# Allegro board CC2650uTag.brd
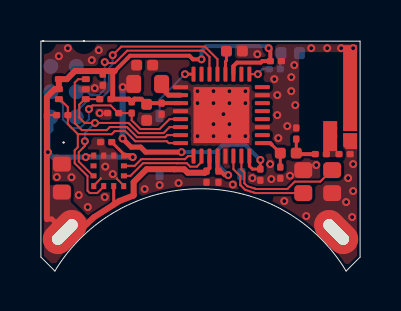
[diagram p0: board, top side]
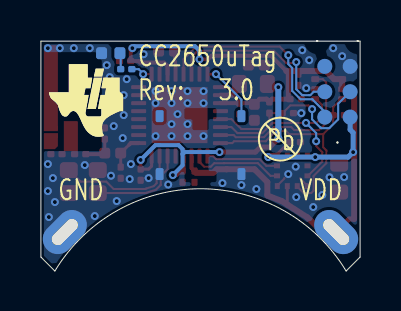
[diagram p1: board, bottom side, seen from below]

Outline 16 x 11.5 mm; copper layers: TOP, BOTTOM. Coordinates in mm from the lower left corner of the outline.
Outline path: 0,11.5 0,0.7 0.7,0 arc(8,4.12) 15.3,0 16,0.7 16,11.5 0,11.5

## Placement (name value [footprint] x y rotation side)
A1  2450AT07A0100  [ANTENNA_2450AT07A0100N]  14.7 6.75 0 top
C1  22uF  [CAPC1608X90L]  1.05 3.95 90 top
C2  100nF  [CAPC0603X35L]  11.5 10.5 0 top
C3  100nF  [CAPC0603X35L]  8.3 5 270 top
C4  10uF  [CAPC1005X60L]  5.3 8.34 270 top
C5  100nF  [CAPC0603X35L]  6.05 8.4 270 top
C6  10uF  [CAPC1005X60L]  4.8 10.3 0 top
C7  100nF  [CAPC0603X35L]  8.9 5 270 top
C8  100nF  [CAPC0603X35L]  11 5.1 270 top
C9  100nF  [CAPC0603X35L]  3.9 7.9 180 top
C11  1.2pF  [CAPC0603X35L]  12 5.2 270 top
C12  1.2pF  [CAPC0603X35L]  12.8 6.6 90 top
C13  12pF  [CAPC0603X35L]  13.75 5.85 0 top
C14  DNM  [CAPC0603X35L]  15.5 5.85 180 top
C19  1uF  [CAPC1005X60L]  9.3 11 0 top
C21  100nF  [CAPC0603X35L]  3.55 6.45 180 top
C41  100nF  [CAPC0603X35L]  3.1 9.85 270 top
CR1  LWQH8G-Q2S2-3K5L-1  [LED_LWQH8GQ2S23K5L1L]  12.96 10.9 180 bottom
L1  10uH  [INDC1608X100L]  6.05 9.36 180 top
L11  2nH  [INDC1005X60L]  12 5.9 0 top
NOREF  -  []  0 6.32 0 top
NOREF#2  -  []  15.3 0 90 top
NOREF#3  -  []  14.6 10.35 180 bottom
P1  TC2030-CTX-NL  [TAGCONNECT_TC2030-CTX-NLL]  0.5 7.7 90 bottom
R1  102k  [RESC0603X35L]  4.55 7.9 90 top
R2  2.2k  [RESC0603X35L]  1.35 7.8 180 top
R3  2.2k  [RESC0603X35L]  2.95 8.6 0 top
R4  150  [RESC0603X35L]  12 10.1 180 bottom
SP1  CUSTOM_BATTERY_CONN  [PAD_S2800OBL5000_800M3000]  1.2 1.95 315 top
SP2  CUSTOM_BATTERY_CONN  [PAD_S2800OBL5000_800M3000]  14.8 1.95 45 top
SW2  EVQP6LB55  [SW_EVQP6LB55L]  5.95 4.85 90 bottom
U1  CC26XX_4X4  [QFNFC40P400X400X100-33L]  11.1 6.4 90 top
U2  KX022-1020  [LGAFC12S50P200X200X100]  2.65 4.25 0 top
U4  TMP102  [SOTFL50P160X60-6AL]  2.25 8.6 90 top
Y2  24MHz  [XTAL_FA128L]  13.15 3.9 0 top

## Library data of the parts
A1 = ANTENNA_CERAMIC_4: alternate symbols: (ANTENNA_2450AT07A0100L,ANTENNA_2450AT07A0100M)
C1 = CAPACITOR: alternate symbols: (CAPC1608X90L,CAPC1608X90M)
C2 C3 C5 C7-C9 C11-C13 C21 C41 = CAPACITOR: alternate symbols: (CAPC0603X35L,CAPC0603X35M)
C4 C6 C19 = CAPACITOR: alternate symbols: (CAPC1005X60L,CAPC1005X60M)
C14 = CAPACITOR: alternate symbols: (CAPC0603X35L,CAPC0603X35N)
CR1 = LED: User Part Number: #PN; alternate symbols: (LED_LWQH8GQ2S23K5L1L,LED_LWQH8GQ2S23K5L1M)
L1 = INDUCTOR: alternate symbols: (INDC1608X100L,INDC1608X100M)
L11 = INDUCTOR: alternate symbols: (INDC1005X60L,INDC1005X60M)
P1 = CONN_IDC_TC2030-CTX-NL_0: alternate symbols: (TAGCONNECT_TC2030-CTX-NLL,TAGCONNECT_TC2030-CTX-NLM)
R1-R4 = RESISTOR: alternate symbols: (RESC0603X35L,RESC0603X35M)
SP1 SP2 = SINGLEPAD
SW2 = SWITCH_TACT: User Part Number: #PN; alternate symbols: (SW_EVQP6LB55L,SW_EVQP6LB55M)
U1 = IC_RF_CC26XX_QFN32_2: alternate symbols: (QFNFC40P400X400X100-33L,QFNFC40P400X400X100-33M)
U2 = IC_ACC_KX022-1020_LGA12: User Part Number: #PN
U4 = IC_PERIPH_TMP102_SOT563: User Part Number: #PN; alternate symbols: (SOTFL50P160X60-6AL,SOTFL50P160X60-6AM)
Y2 = XTAL_4: alternate symbols: (XTAL_FA128L,XTAL_FA128M)

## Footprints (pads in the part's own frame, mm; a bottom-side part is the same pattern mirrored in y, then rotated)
ANTENNA_2450AT07A0100N
  custom 0.062x0.062 smd: 1(0,0) 2(0.6,0) 3(0.6,0.4) 4(0,0.4)
CAPC0603X35L
  custom 0.08x0.08 smd: 1(0,0) 2(0.56,0)
CAPC1005X60L
  custom 0.135x0.135 smd: 1(0,0) 2(0.8,0)
CAPC1608X90L
  custom 0.188x0.188 smd: 1(0,0) 2(1.4,0)
INDC1005X60L
  custom 0.135x0.135 smd: 1(0,0) 2(0.8,0)
INDC1608X100L
  custom 0.188x0.188 smd: 1(0,0) 2(1.4,0)
LED_LWQH8GQ2S23K5L1L
  custom 0.138x0.138 smd: 1(0,0) 2(0.92,0)
LGAFC12S50P200X200X100
  rect 0.25x0.3 smd: 1(0,0) 2(0.5,0) 3(1,0) 4(1.5,0) 7(1.5,1.526) 8(1,1.526) 9(0.5,1.526) 10(0,1.526)
  rect 0.3x0.25 smd: 5(1.512,0.513) 6(1.512,1.013) 11(-0.012,1.013) 12(-0.012,0.513)
PAD_S2800OBL5000_800M3000
  oval 1.5x2.5 hole 0.6x1.6: 1(0,0)
QFNFC40P400X400X100-33L
  custom 0.05x0.05 smd: 1(0,0) 2(0.4,0) 3(0.8,0) 4(1.2,0) 5(1.6,0) 6(2,0) 7(2.4,0) 8(2.8,0) 9(3.45,0.65) 10(3.45,1.05) 11(3.45,1.45) 12(3.45,1.85) 13(3.45,2.25) 14(3.45,2.65) 15(3.45,3.05) 16(3.45,3.45) 17(2.8,4.1) 18(2.4,4.1) 19(2,4.1) 20(1.6,4.1) 21(1.2,4.1) 22(0.8,4.1) 23(0.4,4.1) 24(0,4.1) 25(-0.65,3.45) 26(-0.65,3.05) 27(-0.65,2.65) 28(-0.65,2.25) 29(-0.65,1.85) 30(-0.65,1.45) 31(-0.65,1.05) 32(-0.65,0.65)
  rect 2.799x2.799 smd: 33(1.4,2.05)
RESC0603X35L
  custom 0.08x0.08 smd: 1(0,0) 2(0.56,0)
SOTFL50P160X60-6AL
  custom 0.075x0.075 smd: 1(0,0) 2(0.5,0) 3(1,0) 4(1,1.35) 5(0.5,1.35) 6(0,1.35)
SW_EVQP6LB55L
  custom 0.1x0.1 smd: 1(0,0) 2(2.9,0) 3(2.9,4.1) 4(0,4.1)
TAGCONNECT_TC2030-CTX-NLL
  round 0.1 hole 1 unplated: (-1.27,0.635) (3.81,-0.381) (3.81,1.651)
  round 0.75 smd: 1(0,0) 2(0,1.27) 3(1.27,0) 4(1.27,1.27) 5(2.54,0) 6(2.54,1.27)
XTAL_FA128L
  custom 0.2x0.2 smd: 1(0,0) 2(1.45,0) 3(1.45,1.15) 4(0,1.15)

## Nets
GND: A1.2(GND#2) A1.3(GND#3) C1.2 C2.2 C3.2 C4.2 C5.2 C6.2 C7.2 C8.2 C9.2 C11.2 C12.2 C14.1 C19.2 C21.2 C41.2 CR1.1(C) P1.5(GND) SP2.1 SW2.1 SW2.4 U1.3(VSS#3) U1.7(VSS#7) U1.17(VSS#17) U1.20(VSS#20) U1.29(VSS#29) U1.33(EGP) U2.1(SDO/ADDR) U2.4(TRIG) U2.8(GND#8) U2.9(GND#9) U4.2(GND) Y2.2 Y2.4
VDDR: C6.1 C7.1 C8.1 L1.2 U1.28(VDDR#28) U1.32(VDDR#32)
VDDS: C1.1 C2.1 C3.1 C4.1 C5.1 C21.1 C41.1 P1.1(VDD) R1.2 R2.2 R3.2 SP1.1 U1.11(VDDS2) U1.19(VDDS_DCDC) U1.27(VDDS) U2.3(IOVDD) U2.7(VDD) U2.10(NCS) U4.4(ADD0) U4.5(V+)
ACCINT1: U1.26(DIO_9) U2.5(INT1)
ACCINT2: U1.25(DIO_8) U2.6(INT2)
ANT: A1.1 A1.4 C13.2 C14.2
DCDC_SW: L1.1 U1.18(DCDC_SW)
JTAG_TCK: P1.4(TCK) U1.14(JTAG_TCKC)
JTAG_TMS: P1.2(TMS) U1.13(JTAG_TMSC)
NRESET: C9.1 P1.3(NRST) R1.1 U1.21(RESET_N)
SCL: R3.1 U1.22(DIO_5) U2.12(SCLK/SCL) U4.1(SCL)
SDA: R2.1 U1.24(DIO_7) U2.2(SDI/SDA) U4.6(SDA)
TALERT: U1.23(DIO_6) U4.3(ALERT)
N309359: C19.1 U1.12(DCOUPL)
N323476: C11.1 L11.1 U1.1(RF_P)
N323522: C12.1 C13.1 L11.2
N626514: U1.30(X24M_N) Y2.1
N626528: U1.31(X24M_P) Y2.3
N642320: CR1.2(A) R4.1
N642580: R4.2 U1.9(DIO_1)
N644182: SW2.2 U1.16(DIO_4)

Pads without a net: P1 6; SW2 3; U1 2 4 5 6 8 10 15; U2 11

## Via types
v1: diameter 0.4, hole 0.2, TOP to BOTTOM, 75 vias

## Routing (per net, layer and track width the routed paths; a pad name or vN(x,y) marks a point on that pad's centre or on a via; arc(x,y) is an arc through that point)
GND: length 1.1
  TOP w0.102: 3.8,4.65 3.8,4.62 4.15,4.27 U2.4 ; 3,4.65 3,4.62 2.65,4.27 U2.1
  vias: v1(0.8,4.7) v1(0.9,10.75) v1(1.35,11.15) v1(1.53,4.69) v1(1.9,3.8) v1(2.35,3.2) v1(2.55,10.55) v1(2.7,9.15) v1(2.9,11.05) v1(2.95,7.9) v1(3.23,5.22) v1(3.2,3.7) v1(3.6,4.85) v1(5.2,4.1) v1(5.95,4.3) v1(6.9,4.4) v1(7.85,9) v1(7.85,8.4) v1(7.85,6.75) v1(8.65,9) v1(8.65,8.4) v1(8.65,7.35) v1(8.65,6.75) v1(9.15,7.85) v1(9.45,9) v1(9.45,8.4) v1(9.45,7.35) v1(9.45,6.75) v1(9.62,4.33) v1(10.25,9) v1(10.25,8.4) v1(10.25,6.75) v1(10.6,4.65) v1(10.85,10.85) v1(11.49,5.35) v1(11.55,4.6) v1(11.7,9.6) v1(11.85,8.8) v1(11.85,7.8) v1(11.9,6.65) v1(12.2,3.5) v1(12.35,7.25) v1(12.49,4.77) v1(12.55,9.7) v1(12.55,9) v1(12.7,10.3) v1(12.75,8.3) v1(13.3,2.75) v1(13.55,11.15) v1(13.8,5.3) v1(14.35,11.15) v1(15.05,11.15) v1(15.3,3.45) v1(15.4,4.65) v1(15.65,11.15) v1(15.65,5.35) v1(15.65,4) v1(15.6,2.7)
VDDR: length 14.6
  TOP w0.15: v1(11,5.56) C8.1 10.6,5.1 10.45,5.25 U1.32
  TOP w0.2: U1.28 8.85,5.05 C7.1 9,5 9.2,4.8 v1(9.39,4.8)
  TOP w0.25: v1(4.09,6.63) 4.52,6.2 5,6.2 5.25,5.95 v1(7.05,5.95)
  BOTTOM w0.2: v1(9.39,4.8) 8.9,5.29 8.9,5.85 ; 8.9,5.85 8.9,6.1 9.1,6.3 10.08,6.3 10.08,6.3 10.26,6.3 v1(11,5.56) ; 8.9,5.85 8.8,5.95 7.48,5.95 7.48,5.95 v1(7.05,5.95)
  BOTTOM w0.3: v1(4.09,6.63) 4.09,7.11 4.1,7.12 v1(4.1,9.2)
VDDS: length 47.7
  TOP w0.102: v1(2.25,5.7) 2.3,5.7 2.31,5.71 2.36,5.71 2.43,5.78 U2.10 ; 1.25,1.95 1.31,2.01 ; R2.2 0.35,7.8 0.3,7.85
  TOP w0.15: U2.7 4.15,5.85 C21.1 ; U2.3 3.65,3.33
  TOP w0.2: v1(8.05,10.59) 7.62,10.59 7.44,10.77 4.47,10.77 3.7,10 ; v1(11.41,11.15) 11.5,11.06 C2.1 11.09,10.5 11.02,10.43 9.83,10.43 9.65,10.25 U1.11 ; 5.04,8.6 C4.1 5.36,8.4 C5.1 U1.19 ; C3.1 8.45,5.15 U1.27
  TOP w0.25: U2.7 4.42,5.78 4.5,5.7 v1(4.6,5.7) ; 5.04,8.6 4.69,8.6 R1.2 4.41,8.6 R3.2 3.6,8.69 3.6,9.9 3.7,10 ; SP1.1 0.55,2.6 0.3,2.6 ; v1(0.35,5.95) 0.3,5.95 ; 3.65,3.33 3.62,3.31
  TOP w0.3: 0.3,2.6 0.3,7.85 0.3,7.85 0.3,7.85 0.3,8.71 0.69,9.1 U4.5 U4.4 1.3,9.6 1.7,10 3.1,10 ; 3.1,10 3.7,10 ; 3.1,10 C41.1 ; SP1.1 1.88,1.95 2.65,2.69 3.62,3.31 3.94,3.5 4.63,3.77 4.65,3.8 4.65,4.45 5.29,5.09 6.69,5.09 6.69,5.09 7.19,5.09 7.36,4.92 8.22,4.92 C3.1
  BOTTOM w0.2: v1(11.41,11.15) 11.31,11.25 8.28,11.25 8.05,11.02 v1(8.05,10.59)
  BOTTOM w0.25: v1(4.6,5.7) v1(2.25,5.7) 0.6,5.7 v1(0.35,5.95) 0.35,6.92 0.5,7.07 P1.1
ACCINT1: length 4.6
  TOP w0.102: U1.26 8.05,5.46 7.81,5.22 7.49,5.22 7.31,5.39 6.82,5.39 6.82,5.4 5.12,5.4 4.49,4.76 U2.5
ACCINT2: length 3.7
  TOP w0.102: U2.6 4.7,5.26 5.04,5.6 6.9,5.6 6.9,5.6 7.2,5.6 7.2,5.6 7.22,5.6 7.37,5.75 U1.25
DCDC_SW: length 1.3
  TOP w0.25: U1.18 6.4,8.8 6.05,9.15 L1.1
JTAG_TCK: length 9.5
  TOP w0.102: v1(3.2,10.45) 3.25,10.41 3.7,10.41 4.33,11.02 8.14,11.02 8.45,10.71 U1.14
  BOTTOM w0.102: v1(3.2,10.45) 3.2,9.1 2.9,8.8 2.85,8.8 2.85,8.8 2.55,8.8 2.55,8.8 2.49,8.8 2.32,8.97 P1.4
JTAG_TMS: length 10.6
  TOP w0.102: v1(3.6,10.8) 4.03,11.23 8.22,11.23 8.85,10.6 U1.13
  BOTTOM w0.102: P1.2 1.77,7.97 2.39,8.59 2.98,8.59 3.4,9.01 3.4,10.16 3.6,10.36 v1(3.6,10.8)
NRESET: length 9.4
  TOP w0.102: U1.21 6.45,7.6 5.95,7.1 4.99,7.1 4.55,7.54 R1.1 C9.1 3.88,7.9 3.49,8.29 2.59,8.29 2.41,8.11 v1(2.41,8.1)
  BOTTOM w0.102: v1(2.41,8.1) 2.41,7.59 1.99,7.17 1.97,7.17 1.95,7.15 1.54,7.15 1.1,7.59 1.1,8.37 P1.3
SCL: length 10.6
  TOP w0.102: U2.12 2.61,4.76 1.9,5.48 1.9,5.95 2.2,6.26 v1(2.2,6.49) ; U1.22 6.45,7.2 6.15,6.9 4.9,6.9 4.45,7.35 4.39,7.41 3.09,7.41 3.09,7.41 v1(2.71,7.41) 2.19,7.41 1.92,7.68 1.92,8.32 2.2,8.6 U4.1 R3.1
  BOTTOM w0.102: v1(2.2,6.49) 2.2,6.9 v1(2.71,7.41)
SDA: length 11.8
  TOP w0.102: U4.6 0.95,8.6 1.35,8.2 R2.1 1.35,7.35 1.85,6.85 ; 1.85,6.85 1.85,6.19 1.69,6.03 1.69,5.39 2.33,4.75 2.33,4.02 2.45,3.9 2.83,3.9 3.15,4.22 U2.2 ; 1.85,6.85 1.85,6.85 3.55,6.85 3.7,7 4.22,7 4.73,6.49 6.32,6.49 6.41,6.4 U1.24
TALERT: length 8.4
  TOP w0.102: U1.23 6.33,6.8 6.23,6.7 4.82,6.7 4.36,7.15 4.31,7.2 3.45,7.2 3.3,7.05 2.05,7.05 1.7,7.4 1.7,9.43 1.87,9.6 U4.3
N309359: length 1.2
  TOP w0.15: U1.12 9.25,10.48 9.3,10.53 C19.1
N323476: length 1.8
  TOP w0.15: C11.1 L11.1 11.99,5.9 11.56,6.33
  TOP w0.2: U1.1 11.49,6.4 11.56,6.33
N323522: length 1.7
  TOP w0.15: C12.1 L11.2
  TOP w0.2: L11.2 12.85,5.85 C13.1
N626514: length 4.9
  TOP w0.102: U1.30 9.65,5.1 9.99,4.75 9.99,4.31 10.23,4.07 10.69,3.92 10.76,3.9 Y2.1
N626528: length 6.3
  TOP w0.102: Y2.3 14.58,5.05 14,4.47 12.72,4.47 12.35,4.1 10.79,4.1 10.71,4.13 10.34,4.25 10.2,4.39 10.2,4.94 10.05,5.08 U1.31
N642320: length 0.8
  BOTTOM w0.102: CR1.2 12,10.86 R4.1
N642580: length 1.1
  TOP w0.102: v1(10.88,9.85) U1.9
  BOTTOM w0.102: v1(10.88,9.85) 10.88,9.88 11.1,10.1 R4.2
N644182: length 3.1
  TOP w0.15: v1(7.22,9.85) U1.16
  BOTTOM w0.102: v1(7.22,9.85) 5.95,8.58 SW2.2

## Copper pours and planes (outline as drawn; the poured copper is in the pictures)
GND on TOP (solid shape): 15.85,7 15.15,7 15.15,11.3 15.85,11.3
GND on TOP: 15.33,0.24 8,4.27 0.67,0.24 0.15,0.76 0.15,11.35 15.85,11.35 15.85,0.76 ; 2 cut-outs
GND on BOTTOM: 15.33,0.24 8,4.27 0.67,0.24 0.15,0.76 0.15,11.35 15.85,11.35 15.85,0.76 ; 1 cut-out
VDDR on TOP: 3.9,10.6 3.9,8.9 5,8.9 5,10.6
VDDS on TOP: 2.58,2.37 1.54,1.38 0.67,0.24 0.15,0.76 0.15,4.25 0.15,4.3 1.25,4.3 1.5,4.05 1.5,3.45
ANT on TOP (solid shape): 14.85,6 14.15,6 14.15,7.5 14.85,7.5

Small or netless copper shapes (teardrops, artwork), in the pictures only: 2 on TOP

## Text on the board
Ref Des/Silkscreen Bottom: VDD | Pb | CC2650uTag | Rev:   3.0 | GND
XSECTION_CHART: L1: TOP CONDUCTOR - COPPER 0.035 MM | *  DIELECTRIC - FR-4 0.53 MM | L2: BOTTOM CONDUCTOR - COPPER 0.035 MM | DESIGN CROSS SECTION CHART | ___________________________ | TOTAL THICKNESS 0.6 MM
User.6: FIGURE | SIZE | 0.2 | 1.0 | 1.6x0.6 | DRILL CHART: TOP to BOTTOM | ALL UNITS ARE IN MILLIMETERS | PLATED | NON-PLATED | QTY | 75 | 3 | 1
